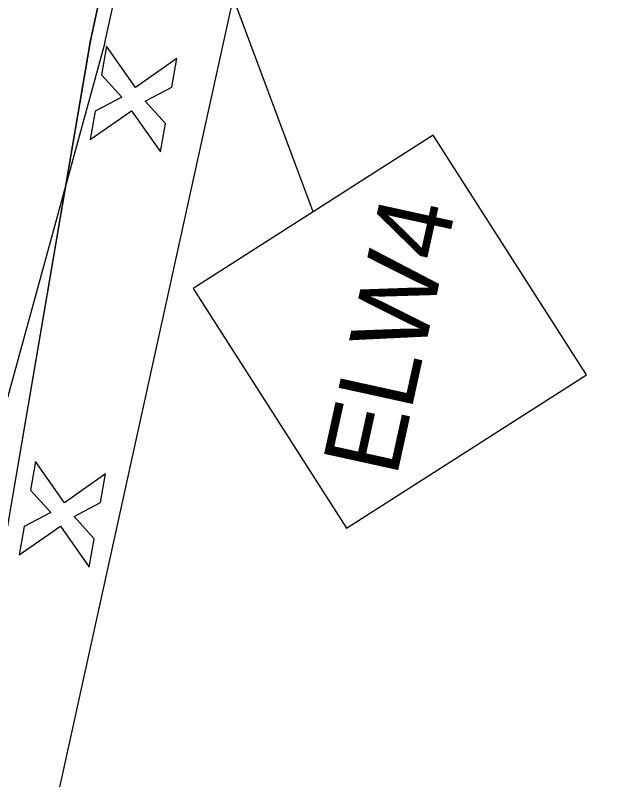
# Model space of a CAD drawing. Extents: x 14104283 to 14121738, y 8635219 to 8671666.
# Drawn here: x 14107682.2 to 14107738, y 8638407.3 to 8638479.9 of the extents above; entities that cross this region are included whole.
import ezdxf

# ---------------------------------------------------------------- set-up
doc = ezdxf.new("R2010")
doc.units = 0
for name, color, linetype in [('Cell', 7, 'Continuous'), ('Default', 7, 'Continuous'), ('dsnPaintExistingEdgeLineRightWhite', 7, 'Continuous'), ('dsnPaintPlaceEdgeLineRightWhite', 7, 'Continuous'), ('dsnPaintRemoveEdgeLineYellow', 7, 'Continuous'), ('dsnStdLabel', 7, 'Continuous'), ('dsnTapePlaceChannelizingLaneWhite', 7, 'Continuous'), ('dsnTapeRemoveChannelizingYellow', 7, 'Continuous')]:
    doc.layers.add(name, color=color, linetype=linetype)

msp = doc.modelspace()

# ---------------------------------------------------------------- linework, layer by layer
at = {"layer": 'Cell'}
for p, q in [((14107690.843, 8638476.965), (14107690.37, 8638474.256)), ((14107693.587, 8638473.06), (14107690.843, 8638476.965)), ((14107697.492, 8638475.804), (14107693.587, 8638473.06)), ((14107697.019, 8638473.095), (14107697.492, 8638475.804)), ((14107690.37, 8638474.256), (14107692.285, 8638472.145)), ((14107694.502, 8638471.758), (14107697.019, 8638473.095)), ((14107692.285, 8638472.145), (14107689.768, 8638470.808)), ((14107696.417, 8638469.647), (14107694.502, 8638471.758)), ((14107689.295, 8638468.099), (14107693.2, 8638470.843)), ((14107689.768, 8638470.808), (14107689.295, 8638468.099)), ((14107693.2, 8638470.843), (14107695.944, 8638466.938)), ((14107695.944, 8638466.938), (14107696.417, 8638469.647)), ((14107684.098, 8638437.538), (14107683.625, 8638434.829)), ((14107686.842, 8638433.632), (14107684.098, 8638437.538)), ((14107690.747, 8638436.377), (14107686.842, 8638433.632)), ((14107690.274, 8638433.668), (14107690.747, 8638436.377)), ((14107683.625, 8638434.829), (14107685.54, 8638432.718)), ((14107687.757, 8638432.331), (14107690.274, 8638433.668)), ((14107685.54, 8638432.718), (14107683.023, 8638431.381)), ((14107689.672, 8638430.22), (14107687.757, 8638432.331)), ((14107682.55, 8638428.672), (14107686.455, 8638431.416)), ((14107683.023, 8638431.381), (14107682.55, 8638428.672)), ((14107686.455, 8638431.416), (14107689.199, 8638427.511)), ((14107689.199, 8638427.511), (14107689.672, 8638430.22))]:
    msp.add_line(p, q, dxfattribs=at)
at = {"layer": 'Default'}
for p, q in [((14107719.488, 8638614.203), (14107689.297, 8638477.497)), ((14107689.297, 8638477.497), (14107647.954, 8638235.834))]:
    msp.add_line(p, q, dxfattribs=at)
at = {"layer": 'dsnPaintExistingEdgeLineRightWhite'}
msp.add_line((14107468.786, 8637415.993), (14107828.524, 8639053.566), dxfattribs=at)
at = {"layer": 'dsnPaintPlaceEdgeLineRightWhite'}
msp.add_line((14107689.297, 8638477.497), (14107719.488, 8638614.203), dxfattribs=at)
at = {"layer": 'dsnPaintRemoveEdgeLineYellow'}
msp.add_line((14107690.68, 8638477.29), (14107720.435, 8638614.092), dxfattribs=at)
at = {"layer": 'dsnStdLabel'}
msp.add_line((14107710.434, 8638461.242), (14107694.727, 8638503.443), dxfattribs=at)
msp.add_lwpolyline([(14107713.612, 8638431.223), (14107736.356, 8638445.773), (14107721.806, 8638468.517), (14107699.062, 8638453.967)], close=True, dxfattribs=at)
msp.add_arc((14107832.404, 8638639.475), 175.191, 227.16469, 247.50156, dxfattribs=at)
at = {"layer": 'dsnTapePlaceChannelizingLaneWhite'}
msp.add_line((14107648.206, 8638236.233), (14107689.297, 8638477.497), dxfattribs=at)
at = {"layer": 'dsnTapeRemoveChannelizingYellow'}
msp.add_line((14107690.68, 8638477.29), (14107625.689, 8638240.725), dxfattribs=at)

# ---------------------------------------------------------------- texts
at = {"layer": 'dsnStdLabel'}
msp.add_text('ELW4', height=7.2, rotation=77.60784, dxfattribs=at).set_placement((14107718.339, 8638435.96))

doc.saveas('drawing.dxf')
